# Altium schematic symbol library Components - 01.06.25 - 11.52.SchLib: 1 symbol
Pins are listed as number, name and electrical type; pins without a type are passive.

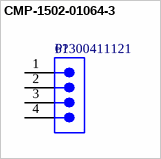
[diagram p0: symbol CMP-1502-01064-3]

## CMP-1502-01064-3
designator P?, comment 61300411121
NexarPartId: 32855522; Operating Supply Voltage: 250V; Pitch: 2.54mm; Contact Resistance: 20mΩ; Number of Positions: 4; Current Rating: 3A; Connector Type: Male Pin; Gender: Male
footprint 61300411121 (Pin Header, pitch 2.54 mm, THT, Vertical, single row, 4p)
pins: 1, 2, 3, 4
